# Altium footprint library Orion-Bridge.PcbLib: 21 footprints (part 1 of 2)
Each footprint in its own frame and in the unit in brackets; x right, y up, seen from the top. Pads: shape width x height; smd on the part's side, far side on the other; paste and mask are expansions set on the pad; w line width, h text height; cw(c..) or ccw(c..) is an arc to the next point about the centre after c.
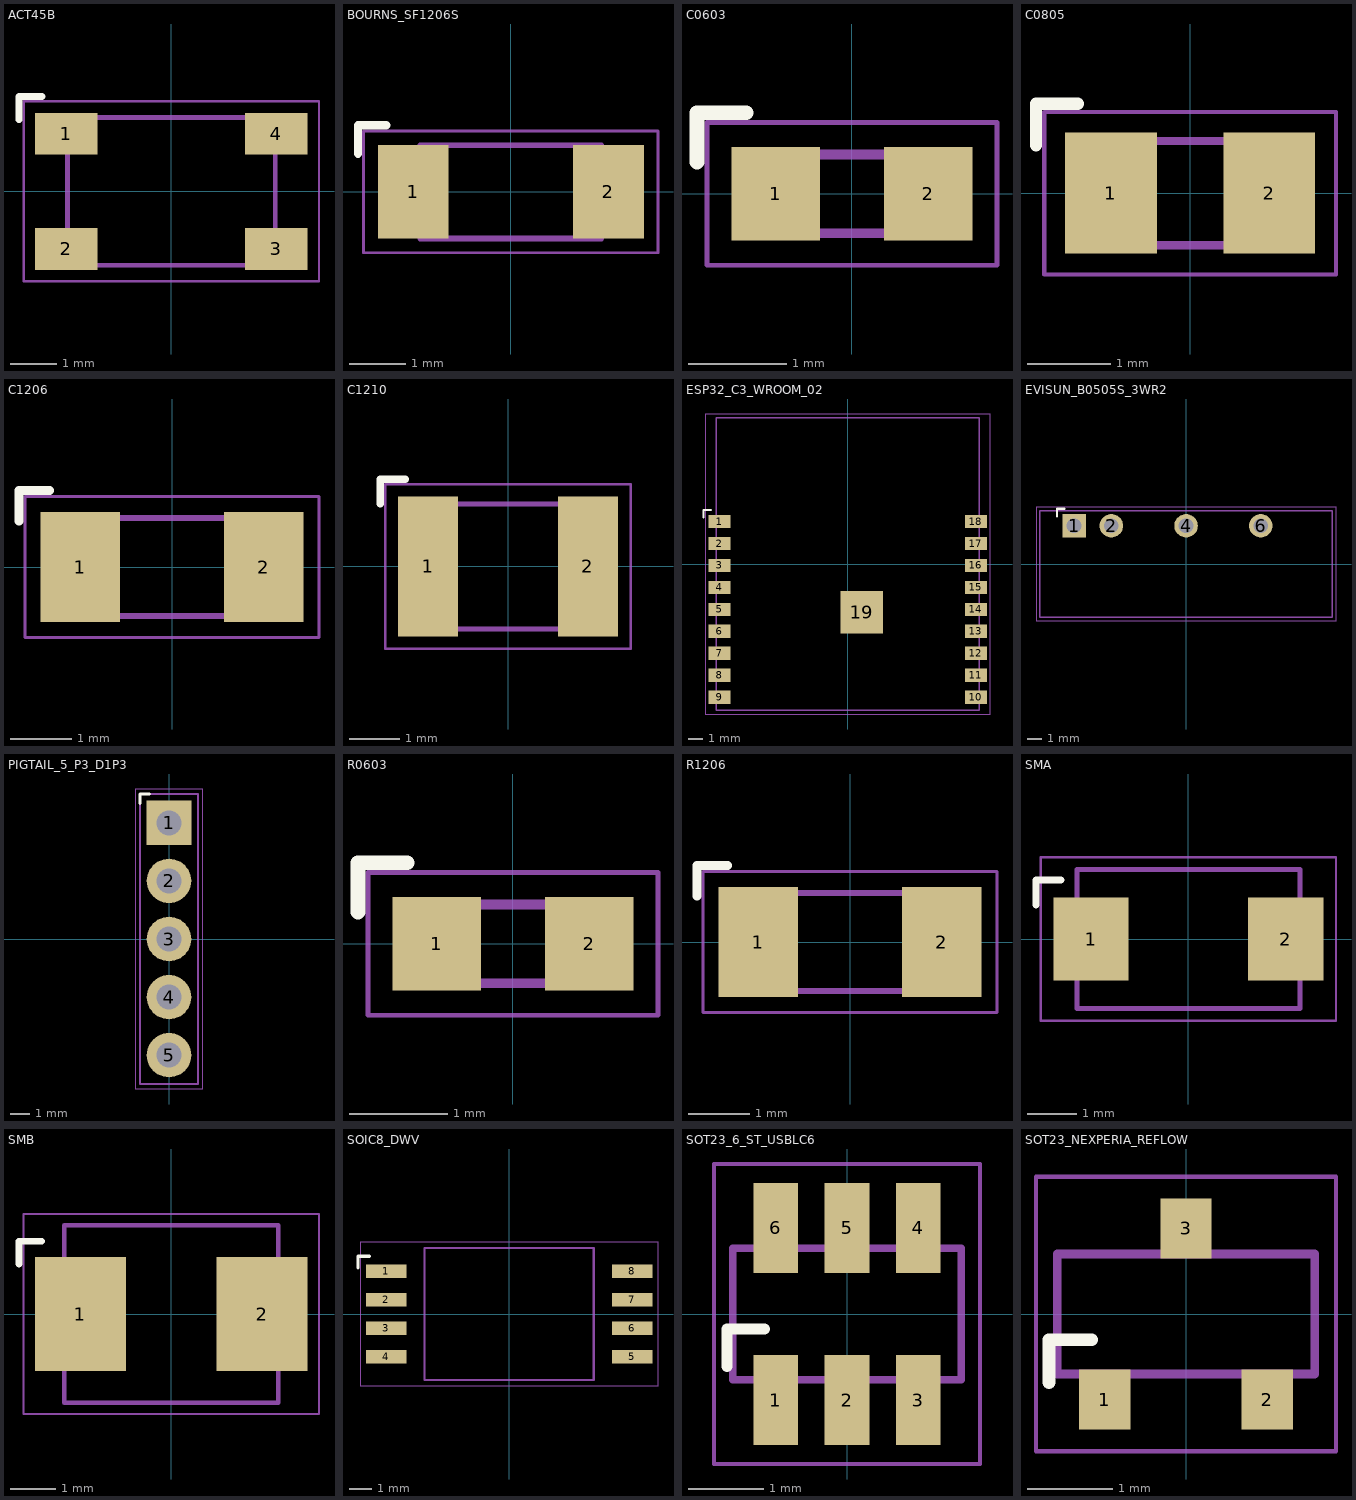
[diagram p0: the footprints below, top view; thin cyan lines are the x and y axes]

## ACT45B [mm] "TDK ACT45B recommended lands; windings 1-4 and 2-3"
height 2.8
pads (4):
  rect 1.35x0.9 smd: 1(-2.275,1.25) 2(-2.275,-1.25) 3(2.275,-1.25) 4(2.275,1.25)
Top Overlay:
  lines w0.15: -3.3,1.55 -3.3,2.05 -2.8,2.05
Component bodies:
  lines w0.1: -2.25,-1.6 2.25,-1.6 2.25,1.6 -2.25,1.6 -2.25,-1.6
Courtyards:
  lines w0.05: -3.2,-1.95 3.2,-1.95 3.2,1.95 -3.2,1.95 -3.2,-1.95
3D body: height 2.8, standoff 0.08, extent -2.25,-1.6 2.25,1.6
3D body: height 0.22, standoff 0.03, extent -2.525,1.01 -1.95,1.49
3D body: height 0.22, standoff 0.03, extent -2.525,-1.49 -1.95,-1.01
3D body: height 0.22, standoff 0.03, extent 1.95,-1.49 2.525,-1.01
3D body: height 0.22, standoff 0.03, extent 1.95,1.01 2.525,1.49

## BOURNS_SF1206S [mm] "Bourns SF-1206S recommended land pattern: total X span 4.7, inner gap 2.2, pad Y 1.65; maximum body envelope. No polarity."
height 0.7
pads (2):
  rect 1.25x1.65 smd: 1(-1.725,0) 2(1.725,0)
Top Overlay:
  lines w0.15: -2.7,0.675 -2.7,1.175 -2.2,1.175
Component bodies:
  lines w0.1: -1.6,-0.825 1.6,-0.825 1.6,0.825 -1.6,0.825 -1.6,-0.825
Courtyards:
  lines w0.05: -2.6,-1.075 2.6,-1.075 2.6,1.075 -2.6,1.075 -2.6,-1.075
3D body: height 0.7, standoff 0.08, extent -1.6,-0.825 1.6,0.825
3D body: height 0.71, standoff 0.03, extent -1.6,-0.833 -1.22,0.833
3D body: height 0.71, standoff 0.03, extent 1.22,-0.833 1.6,0.833

## C0603 [mm] "IPC-style 0603 solder lands; selected MPN dimensions reviewed separately."
height 0.8
pads (2):
  rect 0.9x0.95 smd: 1(-0.775,0) 2(0.775,0)
Top Overlay:
  lines w0.15: -1.575,0.325 -1.575,0.825 -1.075,0.825
Component bodies:
  lines w0.1: -0.8,-0.4 0.8,-0.4 0.8,0.4 -0.8,0.4 -0.8,-0.4
Courtyards:
  lines w0.05: -1.475,-0.725 1.475,-0.725 1.475,0.725 -1.475,0.725 -1.475,-0.725
3D body: height 0.8, standoff 0.08, extent -0.8,-0.4 0.8,0.4
3D body: height 0.81, standoff 0.03, extent -0.8,-0.407 -0.512,0.407
3D body: height 0.81, standoff 0.03, extent 0.512,-0.407 0.8,0.407

## C0805 [mm] "IPC-style 0805 solder lands; selected MPN dimensions reviewed separately."
height 0.8
pads (2):
  rect 1.1x1.45 smd: 1(-0.95,0) 2(0.95,0)
Top Overlay:
  lines w0.15: -1.85,0.575 -1.85,1.075 -1.35,1.075
Component bodies:
  lines w0.1: -1,-0.625 1,-0.625 1,0.625 -1,0.625 -1,-0.625
Courtyards:
  lines w0.05: -1.75,-0.975 1.75,-0.975 1.75,0.975 -1.75,0.975 -1.75,-0.975
3D body: height 0.8, standoff 0.08, extent -1,-0.625 1,0.625
3D body: height 0.81, standoff 0.03, extent -1,-0.633 -0.64,0.633
3D body: height 0.81, standoff 0.03, extent 0.64,-0.633 1,0.633

## C1206 [mm] "IPC-style 1206 solder lands; selected MPN dimensions reviewed separately."
height 1.5
pads (2):
  rect 1.3x1.8 smd: 1(-1.5,0) 2(1.5,0)
Top Overlay:
  lines w0.15: -2.5,0.75 -2.5,1.25 -2,1.25
Component bodies:
  lines w0.1: -1.6,-0.8 1.6,-0.8 1.6,0.8 -1.6,0.8 -1.6,-0.8
Courtyards:
  lines w0.05: -2.4,-1.15 2.4,-1.15 2.4,1.15 -2.4,1.15 -2.4,-1.15
3D body: height 1.5, standoff 0.08, extent -1.6,-0.8 1.6,0.8
3D body: height 1.52, standoff 0.03, extent -1.6,-0.807 -1.22,0.807
3D body: height 1.52, standoff 0.03, extent 1.22,-0.807 1.6,0.807

## C1210 [mm] "Samsung CL32B106KBJNNNE body3.2x2.5mm, nominal1210 land pattern selected."
height 2.7
pads (2):
  rect 1.2x2.8 smd: 1(-1.6,0) 2(1.6,0)
Top Overlay:
  lines w0.15: -2.55,1.25 -2.55,1.75 -2.05,1.75
Component bodies:
  lines w0.1: -1.6,-1.25 1.6,-1.25 1.6,1.25 -1.6,1.25 -1.6,-1.25
Courtyards:
  lines w0.05: -2.45,-1.65 2.45,-1.65 2.45,1.65 -2.45,1.65 -2.45,-1.65
3D body: height 2.7, standoff 0.08, extent -1.6,-1.25 1.6,1.25
3D body: height 2.72, standoff 0.03, extent -1.6,-1.258 -1.22,1.258
3D body: height 2.72, standoff 0.03, extent 1.22,-1.258 1.6,1.258

## ESP32_C3_WROOM_02 [mm] "Espressif WROOM-02 v1.7 Fig11-1. EP19 ground copper with NO paste; optional EP left unsoldered per manufacturer."
height 3.35
pads (19):
  rect 1.5x0.9 smd: 1(-8.75,2.9) 2(-8.75,1.4) 3(-8.75,-0.1) 4(-8.75,-1.6) 5(-8.75,-3.1) 6(-8.75,-4.6) 7(-8.75,-6.1) 8(-8.75,-7.6) 9(-8.75,-9.1) 10(8.75,-9.1) 11(8.75,-7.6) 12(8.75,-6.1) 13(8.75,-4.6) 14(8.75,-3.1) 15(8.75,-1.6) 16(8.75,-0.1) 17(8.75,1.4) 18(8.75,2.9)
  rect 2.9x2.9 smd paste-10: 19(0.96,-3.3)
Top Overlay:
  lines w0.15: -9.85,3.2 -9.85,3.7 -9.35,3.7
Component bodies:
  lines w0.1: -9,-10 9,-10 9,10 -9,10 -9,-10
Courtyards:
  lines w0.05: -9.75,-10.25 9.75,-10.25 9.75,10.25 -9.75,10.25 -9.75,-10.25
3D body: height 0.95, standoff 0.08, extent -9,-10 9,10
3D body: height 3.2, standoff 0.95, extent -7.85,-9.3 7.85,3.07
3D body: height 3.35, standoff 3.2, extent -7.85,-9.3 7.85,3.07
3D body: height 0.98, standoff 0.06, extent -9,2.54 -8.56,3.26
3D body: height 0.98, standoff 0.06, extent 8.56,2.54 9,3.26
3D body: height 0.98, standoff 0.06, extent -9,1.04 -8.56,1.76
3D body: height 0.98, standoff 0.06, extent 8.56,1.04 9,1.76
3D body: height 0.98, standoff 0.06, extent -9,-0.46 -8.56,0.26
3D body: height 0.98, standoff 0.06, extent 8.56,-0.46 9,0.26
3D body: height 0.98, standoff 0.06, extent -9,-1.96 -8.56,-1.24
3D body: height 0.98, standoff 0.06, extent 8.56,-1.96 9,-1.24
3D body: height 0.98, standoff 0.06, extent -9,-3.46 -8.56,-2.74
3D body: height 0.98, standoff 0.06, extent 8.56,-3.46 9,-2.74
3D body: height 0.98, standoff 0.06, extent -9,-4.96 -8.56,-4.24
3D body: height 0.98, standoff 0.06, extent 8.56,-4.96 9,-4.24
3D body: height 0.98, standoff 0.06, extent -9,-6.46 -8.56,-5.74
3D body: height 0.98, standoff 0.06, extent 8.56,-6.46 9,-5.74
3D body: height 0.98, standoff 0.06, extent -9,-7.96 -8.56,-7.24
3D body: height 0.98, standoff 0.06, extent 8.56,-7.96 9,-7.24
3D body: height 0.98, standoff 0.06, extent -9,-9.46 -8.56,-8.74
3D body: height 0.98, standoff 0.06, extent 8.56,-9.46 9,-8.74
3D body: height 0.97, standoff 0.95, extent -6,5.09 6,5.31
3D body: height 0.97, standoff 0.95, extent -6,6.89 6,7.11
3D body: height 0.97, standoff 0.95, extent -6,8.69 6,8.91
3D body: height 0.97, standoff 0.95, extent 5.89,5.2 6.11,7
3D body: height 0.97, standoff 0.95, extent -6.11,7 -5.89,8.8

## EVISUN_B0505S_3WR2 [mm] "EVISUN p4: nominal19.65x7x10.16mm, unspecified body tolerance+/-0.25mm, lead1 x=2.21 from body left, pitch1-2=2.54/2-4=5.08/4-6=5.08mm. Pin row .90mm from long body edge. Bottom view mirrored vertically to PCB TOP: row Y=+2.60mm. Finished holes1.00mm, annulus.30mm. Primary/secondary pad copper gap3.48mm."
height 10.41
pads (4):
  rect 1.6x1.6 hole 1 paste-10: 1(-7.615,2.6)
  round 1.6 hole 1 paste-10: 2(-5.075,2.6) 4(0.005,2.6) 6(5.085,2.6)
Top Overlay:
  lines w0.15: -8.765,3.25 -8.765,3.75 -8.265,3.75
Component bodies:
  lines w0.1: -9.95,-3.625 9.95,-3.625 9.95,3.625 -9.95,3.625 -9.95,-3.625
Courtyards:
  lines w0.05: -10.2,-3.875 10.2,-3.875 10.2,3.875 -10.2,3.875 -10.2,-3.875
3D body: height 10.31, standoff 0.15, extent -9.825,-3.5 9.825,3.5
3D body: height 10.33, standoff 10.31, extent -8.2,-2.55 8.2,2.55
3D body: height 0.45, standoff -2.5, extent -7.865,2.35 -7.365,2.85
3D body: height 0.45, standoff -2.5, extent -5.325,2.35 -4.825,2.85
3D body: height 0.45, standoff -2.5, extent -0.245,2.35 0.255,2.85
3D body: height 0.45, standoff -2.5, extent 4.835,2.35 5.335,2.85

## PIGTAIL_5_P3_D1P3 [mm] "Designed carrier wire-solder interface, 3.0 pitch, 1.3 finished-hole target, 0.5 radial annulus. Pin numbering is logical NMEA: 1 shield, 2 NET-S, 3 NET-C, 4 CAN-H, 5 CAN-L. Cable and strain relief still require a physical selection."
height 3
pads (5):
  rect 2.3x2.3 hole 1.3 paste-10: 1(0,6)
  round 2.3 hole 1.3 paste-10: 2(0,3) 3(0,0) 4(0,-3) 5(0,-6)
Top Overlay:
  lines w0.15: -1.5,7 -1.5,7.5 -1,7.5
Component bodies:
  lines w0.1: -1.5,-7.5 1.5,-7.5 1.5,7.5 -1.5,7.5 -1.5,-7.5
Courtyards:
  lines w0.05: -1.75,-7.75 1.75,-7.75 1.75,7.75 -1.75,7.75 -1.75,-7.75
3D body: height 0.06, standoff 0.03, extent -1.15,4.85 1.15,5.03
3D body: height 0.06, standoff 0.03, extent -1.15,6.97 1.15,7.15
3D body: height 0.06, standoff 0.03, extent -1.15,5.03 -0.97,6.97
3D body: height 0.06, standoff 0.03, extent 0.97,5.03 1.15,6.97
3D body: height 0.06, standoff 0.03, extent -1.15,1.85 1.15,2.03
3D body: height 0.06, standoff 0.03, extent -1.15,3.97 1.15,4.15
3D body: height 0.06, standoff 0.03, extent -1.15,2.03 -0.97,3.97
3D body: height 0.06, standoff 0.03, extent 0.97,2.03 1.15,3.97
3D body: height 0.06, standoff 0.03, extent -1.15,-1.15 1.15,-0.97
3D body: height 0.06, standoff 0.03, extent -1.15,0.97 1.15,1.15
3D body: height 0.06, standoff 0.03, extent -1.15,-0.97 -0.97,0.97
3D body: height 0.06, standoff 0.03, extent 0.97,-0.97 1.15,0.97
3D body: height 0.06, standoff 0.03, extent -1.15,-4.15 1.15,-3.97
3D body: height 0.06, standoff 0.03, extent -1.15,-2.03 1.15,-1.85
3D body: height 0.06, standoff 0.03, extent -1.15,-3.97 -0.97,-2.03
3D body: height 0.06, standoff 0.03, extent 0.97,-3.97 1.15,-2.03
3D body: height 0.06, standoff 0.03, extent -1.15,-7.15 1.15,-6.97
3D body: height 0.06, standoff 0.03, extent -1.15,-5.03 1.15,-4.85
3D body: height 0.06, standoff 0.03, extent -1.15,-6.97 -0.97,-5.03
3D body: height 0.06, standoff 0.03, extent 0.97,-6.97 1.15,-5.03

## R0603 [mm] "IPC-style 0603 solder lands; selected MPN dimensions reviewed separately."
height 0.8
pads (2):
  rect 0.9x0.95 smd: 1(-0.775,0) 2(0.775,0)
Top Overlay:
  lines w0.15: -1.575,0.325 -1.575,0.825 -1.075,0.825
Component bodies:
  lines w0.1: -0.8,-0.4 0.8,-0.4 0.8,0.4 -0.8,0.4 -0.8,-0.4
Courtyards:
  lines w0.05: -1.475,-0.725 1.475,-0.725 1.475,0.725 -1.475,0.725 -1.475,-0.725
3D body: height 0.8, standoff 0.08, extent -0.8,-0.4 0.8,0.4
3D body: height 0.81, standoff 0.03, extent -0.8,-0.407 -0.512,0.407
3D body: height 0.81, standoff 0.03, extent 0.512,-0.407 0.8,0.407

## R1206 [mm] "IPC-style 1206 solder lands; selected MPN dimensions reviewed separately."
height 1.5
pads (2):
  rect 1.3x1.8 smd: 1(-1.5,0) 2(1.5,0)
Top Overlay:
  lines w0.15: -2.5,0.75 -2.5,1.25 -2,1.25
Component bodies:
  lines w0.1: -1.6,-0.8 1.6,-0.8 1.6,0.8 -1.6,0.8 -1.6,-0.8
Courtyards:
  lines w0.05: -2.4,-1.15 2.4,-1.15 2.4,1.15 -2.4,1.15 -2.4,-1.15
3D body: height 1.5, standoff 0.08, extent -1.6,-0.8 1.6,0.8
3D body: height 1.52, standoff 0.03, extent -1.6,-0.807 -1.22,0.807
3D body: height 1.52, standoff 0.03, extent 1.22,-0.807 1.6,0.807

## SMA [mm] "MDD SS12-SS1200 Rev2025A3 p3 / SS22-SS2200 Rev2024A4 p3 suggested SMA pattern: pad1.52x1.68, centrepitch3.93, innergap2.41, totalX5.45mm. Maxbody4.5x2.8x2.45; pin1Kleft,2Aright. Visually checked selected C2480/C14238 PDFs."
height 2.45
pads (2):
  rect 1.52x1.68 smd: 1(-1.965,0) 2(1.965,0)
Top Overlay:
  lines w0.15: -3.075,0.69 -3.075,1.19 -2.575,1.19
Component bodies:
  lines w0.1: -2.25,-1.4 2.25,-1.4 2.25,1.4 -2.25,1.4 -2.25,-1.4
Courtyards:
  lines w0.05: -2.975,-1.65 2.975,-1.65 2.975,1.65 -2.975,1.65 -2.975,-1.65
3D body: height 2.45, standoff 0.08, extent -2.25,-1.4 2.25,1.4
3D body: height 0.2, standoff 0.03, extent -2.54,-0.84 -1.39,0.84
3D body: height 0.2, standoff 0.03, extent 1.39,-0.84 2.54,0.84
3D body: height 2.46, standoff 2.45, extent -1.52,-1.372 -1.27,1.372

## SMB [mm] "BORN SMBJ Series Rev2022-Jan-1-A p7 manufacturer pattern: pad2.0x2.5mm, innergap2.0mm, centres+/-2.0mm; maxbody4.7x3.9x2.5; pin1Kleft,2Aright. Visually checked selected C152104 PDF."
height 2.5
pads (2):
  rect 2x2.5 smd: 1(-2,0) 2(2,0)
Top Overlay:
  lines w0.15: -3.35,1.1 -3.35,1.6 -2.85,1.6
Component bodies:
  lines w0.1: -2.35,-1.95 2.35,-1.95 2.35,1.95 -2.35,1.95 -2.35,-1.95
Courtyards:
  lines w0.05: -3.25,-2.2 3.25,-2.2 3.25,2.2 -3.25,2.2 -3.25,-2.2
3D body: height 2.5, standoff 0.08, extent -2.35,-1.95 2.35,1.95
3D body: height 0.2, standoff 0.03, extent -2.575,-1.05 -1.425,1.05
3D body: height 0.2, standoff 0.03, extent 1.425,-1.05 2.575,1.05
3D body: height 2.51, standoff 2.5, extent -1.582,-1.911 -1.332,1.911

## SOIC8_DWV [mm] "TI DWV0008A manufacturer land pattern; pin 1 upper left"
height 2.8
pads (8):
  rect 1.8x0.6 smd: 1(-5.45,1.905) 2(-5.45,0.635) 3(-5.45,-0.635) 4(-5.45,-1.905) 5(5.45,-1.905) 6(5.45,-0.635) 7(5.45,0.635) 8(5.45,1.905)
Top Overlay:
  lines w0.15: -6.7,2.055 -6.7,2.555 -6.2,2.555
Component bodies:
  lines w0.1: -3.75,-2.925 3.75,-2.925 3.75,2.925 -3.75,2.925 -3.75,-2.925
Courtyards:
  lines w0.05: -6.6,-3.175 6.6,-3.175 6.6,3.175 -6.6,3.175 -6.6,-3.175
3D body: height 2.8, standoff 0.08, extent -3.75,-2.925 3.75,2.925
3D body: height 0.22, standoff 0.03, extent -5.7,1.665 -3.45,2.145
3D body: height 0.22, standoff 0.03, extent -5.7,0.395 -3.45,0.875
3D body: height 0.22, standoff 0.03, extent -5.7,-0.875 -3.45,-0.395
3D body: height 0.22, standoff 0.03, extent -5.7,-2.145 -3.45,-1.665
3D body: height 0.22, standoff 0.03, extent 3.45,-2.145 5.7,-1.665
3D body: height 0.22, standoff 0.03, extent 3.45,-0.875 5.7,-0.395
3D body: height 0.22, standoff 0.03, extent 3.45,0.395 5.7,0.875
3D body: height 0.22, standoff 0.03, extent 3.45,1.665 5.7,2.145
3D body: height 2.82, standoff 2.8, extent -2.38,1.625 -2.12,1.885

## SOT23_6_ST_USBLC6 [mm] "ST USBLC6-2 datasheet Fig22 p12; visually checked manufacturer recommended land pattern."
height 1.45
pads (6):
  rect 0.6x1.2 smd: 1(-0.95,-1.15) 2(0,-1.15) 3(0.95,-1.15) 4(0.95,1.15) 5(0,1.15) 6(-0.95,1.15)
Top Overlay:
  lines w0.15: -1.6,-0.7 -1.6,-0.2 -1.1,-0.2
Component bodies:
  lines w0.1: -1.525,-0.875 1.525,-0.875 1.525,0.875 -1.525,0.875 -1.525,-0.875
Courtyards:
  lines w0.05: -1.775,-2 1.775,-2 1.775,2 -1.775,2 -1.775,-2
3D body: height 1.45, standoff 0.08, extent -1.525,-0.875 1.525,0.875
3D body: height 0.22, standoff 0.03, extent -1.175,-1.4 -0.725,-0.575
3D body: height 0.22, standoff 0.03, extent -0.225,-1.4 0.225,-0.575
3D body: height 0.22, standoff 0.03, extent 0.725,-1.4 1.175,-0.575
3D body: height 0.22, standoff 0.03, extent 0.725,0.575 1.175,1.4
3D body: height 0.22, standoff 0.03, extent -0.225,0.575 0.225,1.4
3D body: height 0.22, standoff 0.03, extent -1.175,0.575 -0.725,1.4
3D body: height 1.47, standoff 1.45, extent -1.045,-0.655 -0.785,-0.395

## SOT23_NEXPERIA_REFLOW [mm] "Nexperia SOT23 reflow footprint Fig10: 0.6 x 0.7 copper lands, 1.9 pin pitch and 2.0 row centres. Drawing is rotated 180 degrees to match existing top-view pin1 lower left, pin2 lower right, pin3 upper centre. Paste suggested0.5 x0.6, mask opening1.0 x1.0; set fabrication-specific expansions accordingly."
height 1.1
pads (3):
  rect 0.6x0.7 smd: 1(-0.95,-1) 2(0.95,-1) 3(0,1)
Top Overlay:
  lines w0.15: -1.6,-0.8 -1.6,-0.3 -1.1,-0.3
Component bodies:
  lines w0.1: -1.5,-0.7 1.5,-0.7 1.5,0.7 -1.5,0.7 -1.5,-0.7
Courtyards:
  lines w0.05: -1.75,-1.6 1.75,-1.6 1.75,1.6 -1.75,1.6 -1.75,-1.6
3D body: height 1.1, standoff 0.08, extent -1.5,-0.7 1.5,0.7
3D body: height 0.22, standoff 0.03, extent -1.175,-1.25 -0.725,-0.4
3D body: height 0.22, standoff 0.03, extent 0.725,-1.25 1.175,-0.4
3D body: height 0.22, standoff 0.03, extent -0.225,0.4 0.225,1.25
3D body: height 1.11, standoff 1.1, extent -1.03,-0.55 -0.77,-0.29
